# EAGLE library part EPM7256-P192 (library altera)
EPM7256E MAX 7000 family
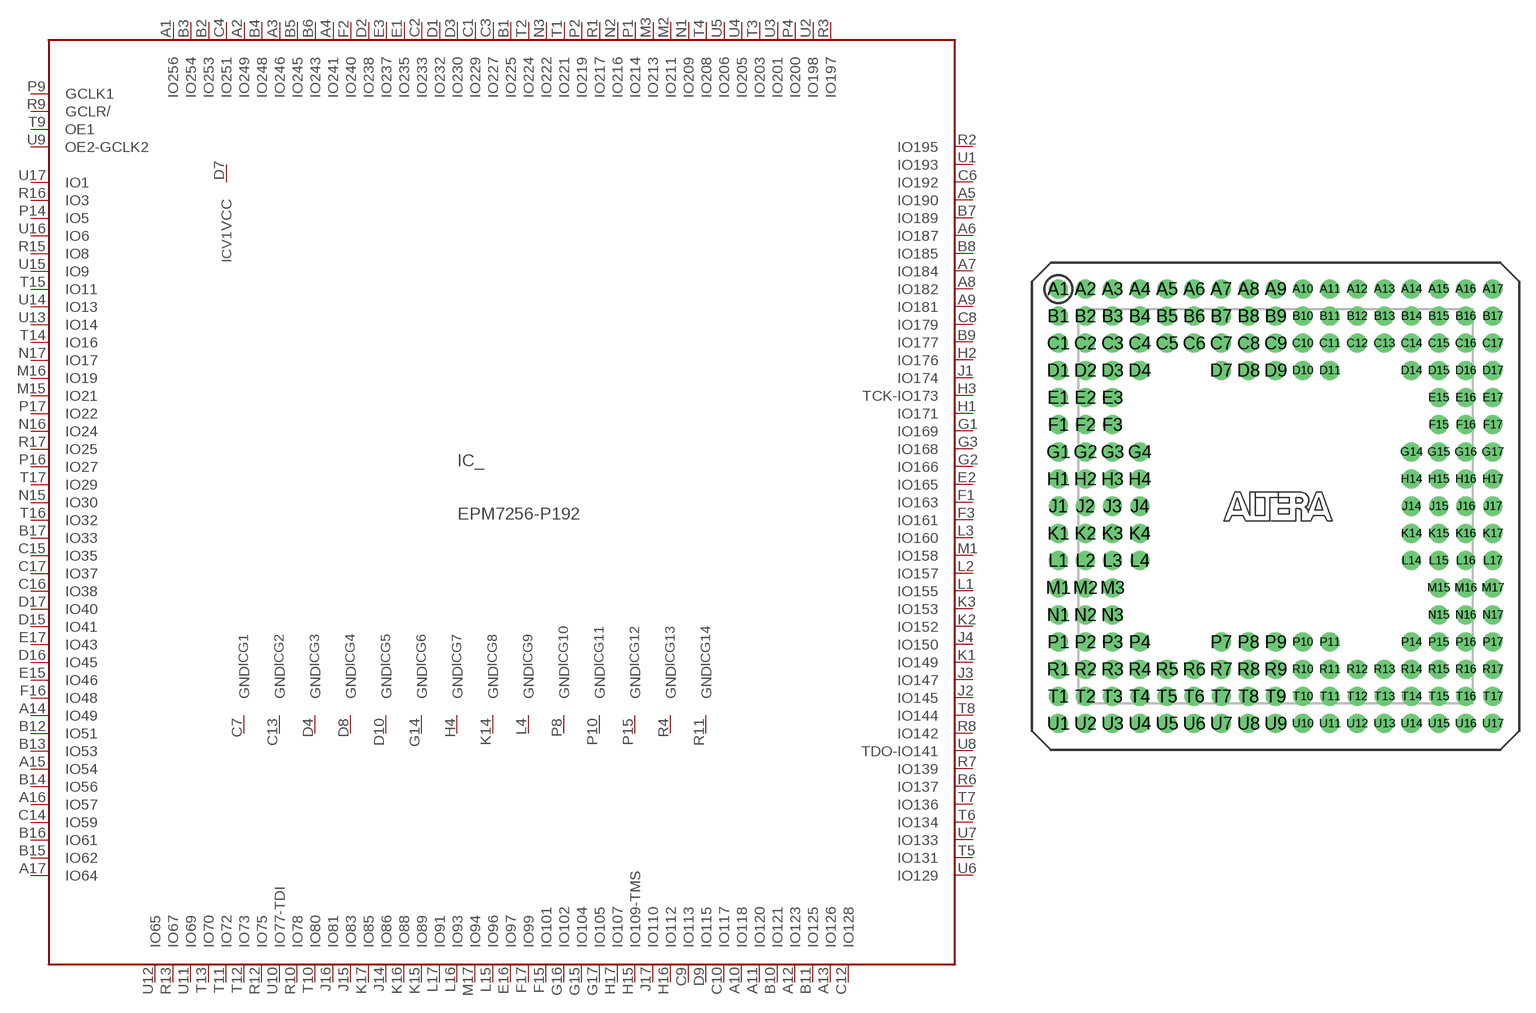
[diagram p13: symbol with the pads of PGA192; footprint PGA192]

Designator prefix IC; gates _=7256R208 G1=GND G2=GND G3=GND G4=GND G5=GND G6=GND G7=GND G8=GND G9=GND G10=GND G11=GND G12=GND G13=GND G14=GND V1=VCCINT V2=VCCINT V3=VCCINT V4=VCCINT V5=VCCIO V6=VCCIO V7=VCCIO V8=VCCIO V9=VCCIO V10=VCCIO V11=VCCIO V12=VCCIO V13=VCCIO V14=VCCIO

## EPM7256-P192 (OC_FARNELL: unknown; OC_NEWARK: unknown)  [PGA192]
A1  _:IO256
A2  _:IO249
A3  _:IO246
A4  _:IO241
A5  _:IO190
A6  _:IO187
A7  _:IO184
A8  _:IO182
A9  _:IO181
A10  _:IO118
A11  _:IO120
A12  _:IO123
A13  _:IO126
A14  _:IO49
A15  _:IO54
A16  _:IO57
A17  _:IO64
B1  _:IO225
B2  _:IO253
B3  _:IO254
B4  _:IO248
B5  _:IO245
B6  _:IO243
B7  _:IO189
B8  _:IO185
B9  _:IO177
B10  _:IO121
B11  _:IO125
B12  _:IO51
B13  _:IO53
B14  _:IO56
B15  _:IO62
B16  _:IO61
B17  _:IO33
C1  _:IO229
C2  _:IO233
C3  _:IO227
C4  _:IO251
C5  V5:VCCIO  pwr
C6  _:IO192
C7  G1:GND  pwr
C8  _:IO179
C9  _:IO113
C10  _:IO117
C11  V6:VCCIO  pwr
C12  _:IO128
C13  G2:GND  pwr
C14  _:IO59
C15  _:IO35
C16  _:IO38
C17  _:IO37
D1  _:IO232
D2  _:IO238
D3  _:IO230
D4  G3:GND  pwr
D7  V1:VCC  pwr
D8  G4:GND  pwr
D9  _:IO115
D10  G5:GND  pwr
D11  V2:VCC  pwr
D14  V7:VCCIO  pwr
D15  _:IO41
D16  _:IO45
D17  _:IO40
E1  _:IO235
E2  _:IO165
E3  _:IO237
E15  _:IO46
E16  _:IO97
E17  _:IO43
F1  _:IO163
F2  _:IO240
F3  _:IO161
F15  _:IO101
F16  _:IO48
F17  _:IO99
G1  _:IO169
G2  _:IO166
G3  _:IO168
G4  V8:VCCIO  pwr
G14  G6:GND  pwr
G15  _:IO104
G16  _:IO102
G17  _:IO105
H1  _:IO171
H2  _:IO176
H3  _:TCK-IO173
H4  G7:GND  pwr
H14  V9:VCCIO  pwr
H15  _:IO109-TMS
H16  _:IO112
H17  _:IO107
J1  _:IO174
J2  _:IO145
J3  _:IO147
J4  _:IO150
J14  _:IO86
J15  _:IO83
J16  _:IO81
J17  _:IO110
K1  _:IO149
K2  _:IO152
K3  _:IO153
K4  V10:VCCIO  pwr
K14  G8:GND  pwr
K15  _:IO89
K16  _:IO88
K17  _:IO85
L1  _:IO155
L2  _:IO157
L3  _:IO160
L4  G9:GND  pwr
L14  V11:VCCIO  pwr
L15  _:IO96
L16  _:IO93
L17  _:IO91
M1  _:IO158
M2  _:IO211
M3  _:IO213
M15  _:IO21
M16  _:IO19
M17  _:IO94
N1  _:IO209
N2  _:IO216
N3  _:IO222
N15  _:IO30
N16  _:IO24
N17  _:IO17
P1  _:IO214
P2  _:IO219
P3  V12:VCCIO  pwr
P4  _:IO200
P7  V3:VCC  pwr
P8  G10:GND  pwr
P9  _:GCLK1  in
P10  G11:GND  pwr
P11  V4:VCC  pwr
P14  _:IO5
P15  G12:GND  pwr
P16  _:IO27
P17  _:IO22
R1  _:IO217
R2  _:IO195
R3  _:IO197
R4  G13:GND  pwr
R5  V13:VCCIO  pwr
R6  _:IO137
R7  _:IO139
R8  _:IO142
R9  _:GCLR/  in
R10  _:IO78
R11  G14:GND  pwr
R12  _:IO75
R13  _:IO67
R14  V14:VCCIO  pwr
R15  _:IO8
R16  _:IO3
R17  _:IO25
T1  _:IO221
T2  _:IO224
T3  _:IO203
T4  _:IO208
T5  _:IO131
T6  _:IO134
T7  _:IO136
T8  _:IO144
T9  _:OE1  in
T10  _:IO80
T11  _:IO72
T12  _:IO73
T13  _:IO70
T14  _:IO16
T15  _:IO11
T16  _:IO32
T17  _:IO29
U1  _:IO193
U2  _:IO198
U3  _:IO201
U4  _:IO205
U5  _:IO206
U6  _:IO129
U7  _:IO133
U8  _:TDO-IO141
U9  _:OE2-GCLK2  in
U10  _:IO77-TDI
U11  _:IO69
U12  _:IO65
U13  _:IO14
U14  _:IO13
U15  _:IO9
U16  _:IO6
U17  _:IO1

## Footprint PGA192 (pad centres in mm)
Pin Grid Array
drill 0.813 pad 1.778 round: A1 -20.32,20.32; A2 -17.78,20.32; A3 -15.24,20.32; A4 -12.7,20.32; A5 -10.16,20.32; A6 -7.62,20.32; A7 -5.08,20.32; A8 -2.54,20.32; A9 0,20.32; A10 2.54,20.32; A11 5.08,20.32; A12 7.62,20.32; A13 10.16,20.32; A14 12.7,20.32; A15 15.24,20.32; A16 17.78,20.32; A17 20.32,20.32; B1 -20.32,17.78; B2 -17.78,17.78; B3 -15.24,17.78; B4 -12.7,17.78; B5 -10.16,17.78; B6 -7.62,17.78; B7 -5.08,17.78; B8 -2.54,17.78; B9 0,17.78; B10 2.54,17.78; B11 5.08,17.78; B12 7.62,17.78; B13 10.16,17.78; B14 12.7,17.78; B15 15.24,17.78; B16 17.78,17.78; B17 20.32,17.78; C1 -20.32,15.24; C2 -17.78,15.24; C3 -15.24,15.24; C4 -12.7,15.24; C5 -10.16,15.24; C6 -7.62,15.24; C7 -5.08,15.24; C8 -2.54,15.24; C9 0,15.24; C10 2.54,15.24; C11 5.08,15.24; C12 7.62,15.24; C13 10.16,15.24; C14 12.7,15.24; C15 15.24,15.24; C16 17.78,15.24; C17 20.32,15.24; D1 -20.32,12.7; D2 -17.78,12.7; D3 -15.24,12.7; D4 -12.7,12.7; D7 -5.08,12.7; D8 -2.54,12.7; D9 0,12.7; D10 2.54,12.7; D11 5.08,12.7; D14 12.7,12.7; D15 15.24,12.7; D16 17.78,12.7; D17 20.32,12.7; E1 -20.32,10.16; E2 -17.78,10.16; E3 -15.24,10.16; E15 15.24,10.16; E16 17.78,10.16; E17 20.32,10.16; F1 -20.32,7.62; F2 -17.78,7.62; F3 -15.24,7.62; F15 15.24,7.62; F16 17.78,7.62; F17 20.32,7.62; G1 -20.32,5.08; G2 -17.78,5.08; G3 -15.24,5.08; G4 -12.7,5.08; G14 12.7,5.08; G15 15.24,5.08; G16 17.78,5.08; G17 20.32,5.08; H1 -20.32,2.54; H2 -17.78,2.54; H3 -15.24,2.54; H4 -12.7,2.54; H14 12.7,2.54; H15 15.24,2.54; H16 17.78,2.54; H17 20.32,2.54; J1 -20.32,0; J2 -17.78,0; J3 -15.24,0; J4 -12.7,0; J14 12.7,0; J15 15.24,0; J16 17.78,0; J17 20.32,0; K1 -20.32,-2.54; K2 -17.78,-2.54; K3 -15.24,-2.54; K4 -12.7,-2.54; K14 12.7,-2.54; K15 15.24,-2.54; K16 17.78,-2.54; K17 20.32,-2.54; L1 -20.32,-5.08; L2 -17.78,-5.08; L3 -15.24,-5.08; L4 -12.7,-5.08; L14 12.7,-5.08; L15 15.24,-5.08; L16 17.78,-5.08; L17 20.32,-5.08; M1 -20.32,-7.62; M2 -17.78,-7.62; M3 -15.24,-7.62; M15 15.24,-7.62; M16 17.78,-7.62; M17 20.32,-7.62; N1 -20.32,-10.16; N2 -17.78,-10.16; N3 -15.24,-10.16; N15 15.24,-10.16; N16 17.78,-10.16; N17 20.32,-10.16; P1 -20.32,-12.7; P2 -17.78,-12.7; P3 -15.24,-12.7; P4 -12.7,-12.7; P7 -5.08,-12.7; P8 -2.54,-12.7; P9 0,-12.7; P10 2.54,-12.7; P11 5.08,-12.7; P14 12.7,-12.7; P15 15.24,-12.7; P16 17.78,-12.7; P17 20.32,-12.7; R1 -20.32,-15.24; R2 -17.78,-15.24; R3 -15.24,-15.24; R4 -12.7,-15.24; R5 -10.16,-15.24; R6 -7.62,-15.24; R7 -5.08,-15.24; R8 -2.54,-15.24; R9 0,-15.24; R10 2.54,-15.24; R11 5.08,-15.24; R12 7.62,-15.24; R13 10.16,-15.24; R14 12.7,-15.24; R15 15.24,-15.24; R16 17.78,-15.24; R17 20.32,-15.24; T1 -20.32,-17.78; T2 -17.78,-17.78; T3 -15.24,-17.78; T4 -12.7,-17.78; T5 -10.16,-17.78; T6 -7.62,-17.78; T7 -5.08,-17.78; T8 -2.54,-17.78; T9 0,-17.78; T10 2.54,-17.78; T11 5.08,-17.78; T12 7.62,-17.78; T13 10.16,-17.78; T14 12.7,-17.78; T15 15.24,-17.78; T16 17.78,-17.78; T17 20.32,-17.78; U1 -20.32,-20.32; U2 -17.78,-20.32; U3 -15.24,-20.32; U4 -12.7,-20.32; U5 -10.16,-20.32; U6 -7.62,-20.32; U7 -5.08,-20.32; U8 -2.54,-20.32; U9 0,-20.32; U10 2.54,-20.32; U11 5.08,-20.32; U12 7.62,-20.32; U13 10.16,-20.32; U14 12.7,-20.32; U15 15.24,-20.32; U16 17.78,-20.32; U17 20.32,-20.32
